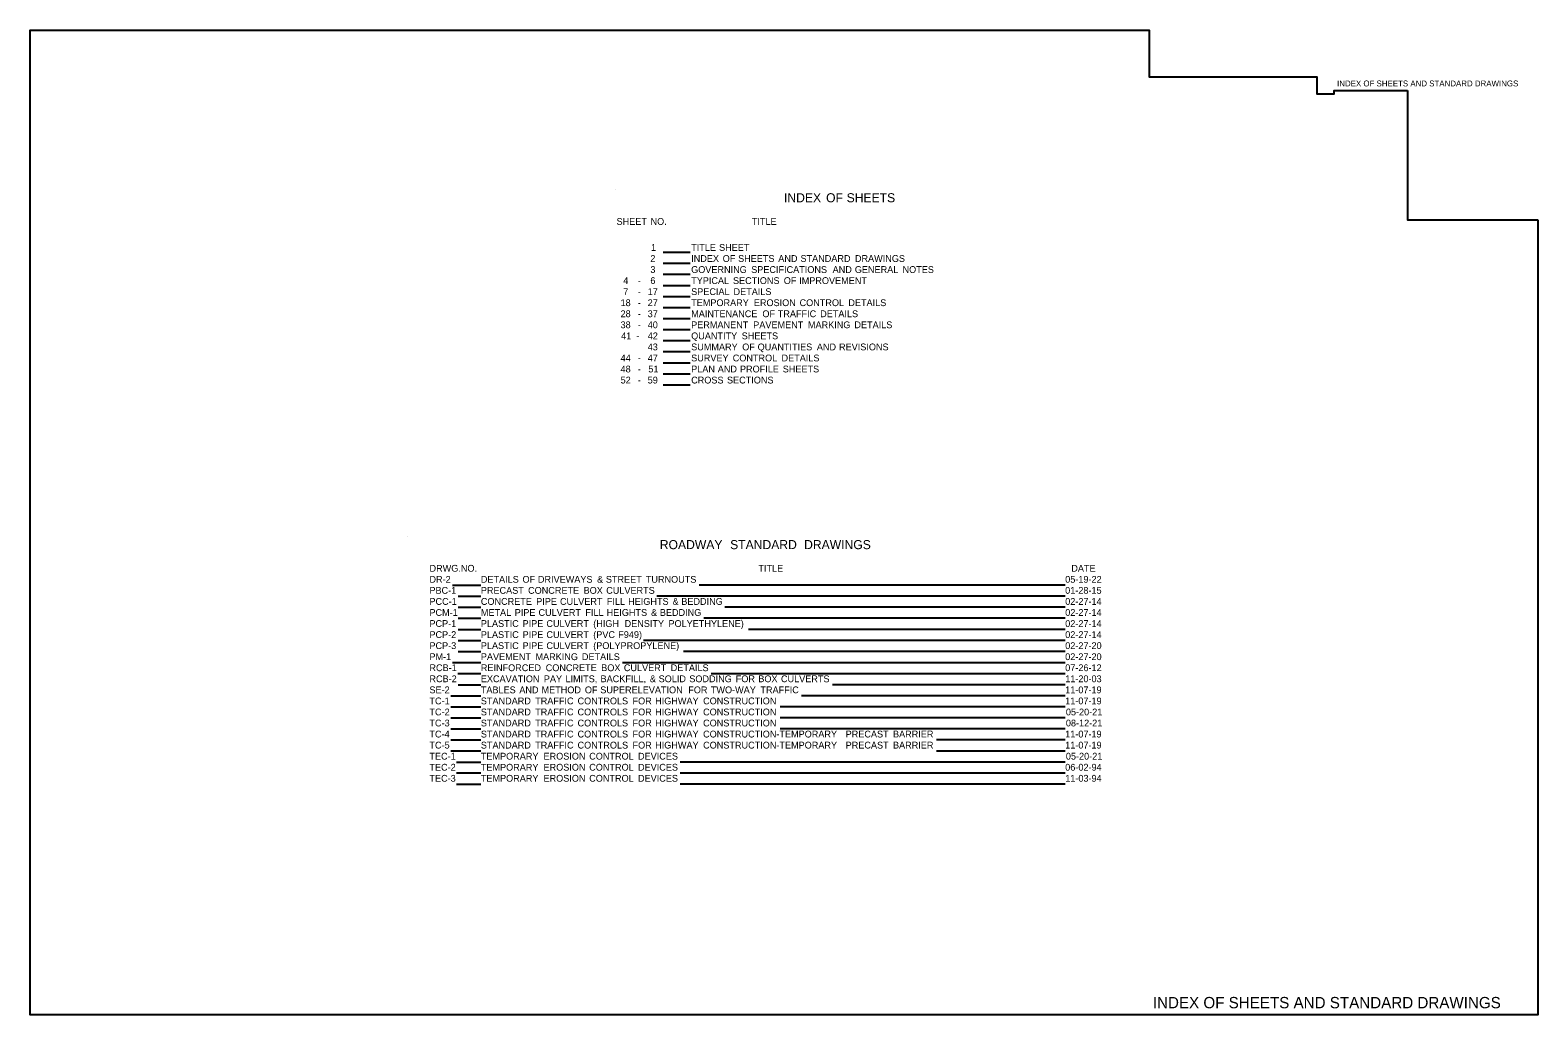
# Model space of a CAD drawing. Extents: x 1955683 to 1956002, y 566394 to 566602.
import ezdxf

# ---------------------------------------------------------------- set-up
doc = ezdxf.new("R2010")
doc.units = 0
for name, color, linetype in [('Default', 7, 'Continuous'), ('R_Border', 7, 'Continuous'), ('R_Border Prem', 7, 'Continuous'), ('STAMP', 7, 'Continuous')]:
    doc.layers.add(name, color=color, linetype=linetype)

msp = doc.modelspace()

# ---------------------------------------------------------------- linework, layer by layer
at = {"layer": 'Default'}
for p, q in [((1955817.31, 566554.97), (1955823.04, 566554.97)), ((1955817.31, 566552.63), (1955823.04, 566552.63)), ((1955817.31, 566550.29), (1955823.04, 566550.29)), ((1955817.31, 566547.95), (1955823.04, 566547.95)), ((1955817.31, 566545.61), (1955823.04, 566545.61)), ((1955817.31, 566543.27), (1955823.04, 566543.27)), ((1955817.31, 566540.93), (1955823.04, 566540.93)), ((1955817.31, 566538.59), (1955823.04, 566538.59)), ((1955817.31, 566536.25), (1955823.04, 566536.25)), ((1955817.31, 566533.91), (1955823.04, 566533.91)), ((1955817.31, 566531.57), (1955823.04, 566531.57)), ((1955817.31, 566529.23), (1955823.04, 566529.23)), ((1955817.31, 566526.89), (1955823.04, 566526.89)), ((1955772.73, 566484.51), (1955778.76, 566484.51)), ((1955824.96, 566484.56), (1955902.43, 566484.56)), ((1955773.96, 566482.16), (1955778.76, 566482.16)), ((1955773.96, 566479.81), (1955778.76, 566479.81)), ((1955815.98, 566482.22), (1955902.43, 566482.22)), ((1955830.36, 566479.87), (1955902.43, 566479.87)), ((1955773.96, 566477.48), (1955778.76, 566477.48)), ((1955825.96, 566477.54), (1955902.43, 566477.54)), ((1955773.96, 566475.12), (1955778.76, 566475.12)), ((1955835.38, 566475.18), (1955902.43, 566475.18)), ((1955773.96, 566472.77), (1955778.76, 566472.77)), ((1955773.96, 566470.44), (1955778.76, 566470.44)), ((1955813.19, 566472.82), (1955902.43, 566472.82)), ((1955821.64, 566470.5), (1955902.43, 566470.5)), ((1955772.73, 566468.12), (1955778.76, 566468.12)), ((1955808.71, 566468.13), (1955902.43, 566468.13)), ((1955773.91, 566465.75), (1955778.76, 566465.75)), ((1955773.97, 566463.41), (1955778.76, 566463.41)), ((1955827.48, 566465.81), (1955902.43, 566465.81)), ((1955853.2, 566463.47), (1955902.43, 566463.47)), ((1955772.44, 566461.07), (1955778.76, 566461.07)), ((1955846.61, 566461.13), (1955902.43, 566461.13)), ((1955772.44, 566458.73), (1955778.76, 566458.73)), ((1955842.11, 566458.79), (1955902.43, 566458.79)), ((1955772.44, 566456.39), (1955778.76, 566456.39)), ((1955772.44, 566454.05), (1955778.76, 566454.05)), ((1955842.11, 566456.45), (1955902.43, 566456.45)), ((1955842.11, 566454.11), (1955902.43, 566454.11)), ((1955772.44, 566451.71), (1955778.76, 566451.71)), ((1955875.18, 566451.77), (1955902.43, 566451.77)), ((1955772.44, 566449.37), (1955778.76, 566449.37)), ((1955875.18, 566449.43), (1955902.43, 566449.43)), ((1955773.62, 566447.03), (1955778.76, 566447.03)), ((1955773.62, 566444.73), (1955778.76, 566444.73)), ((1955820.96, 566447.09), (1955902.43, 566447.09)), ((1955820.96, 566444.74), (1955902.43, 566444.75)), ((1955773.62, 566442.35), (1955778.76, 566442.35)), ((1955820.96, 566442.4), (1955902.43, 566442.41))]:
    msp.add_line(p, q, dxfattribs=at)
at = {"layer": 'R_Border'}
for p, q in [((1955807.24, 566568.3), (1955807.24, 566568.3)), ((1955763.31, 566494.88), (1955763.31, 566494.88))]:
    msp.add_line(p, q, dxfattribs=at)
at = {"layer": 'R_Border Prem'}
for points in [[(1956002.45, 566561.79), (1956002.45, 566393.51), (1955683.38, 566393.51), (1955683.38, 566601.97), (1955920.19, 566601.97), (1955920.19, 566592.09), (1955955.71, 566592.09), (1955955.71, 566588.52), (1955959.35, 566588.52), (1955959.35, 566589.17), (1955974.89, 566589.17)], [(1955974.89, 566589.17), (1955974.89, 566561.79), (1956002.45, 566561.79)]]:
    msp.add_lwpolyline(points, dxfattribs=at)

# ---------------------------------------------------------------- texts
at = {"layer": 'Default'}
for s, height, p in [('INDEX', 1.92, (1955842.92, 566565.53)), (' OF', 1.92, (1955851.11, 566565.53)), (' SHEETS', 1.92, (1955855.46, 566565.53)), ('SHEET', 1.44, (1955807.48, 566560.75)), (' NO.', 1.44, (1955814.14, 566560.75)), ('                        TITLE', 1.44, (1955823.27, 566560.75)), ('1', 1.44, (1955814.77, 566555.25)), ('TITLE', 1.44, (1955823.27, 566555.25)), (' SHEET', 1.44, (1955828.64, 566555.25)), ('2', 1.44, (1955814.63, 566552.91)), ('INDEX', 1.44, (1955823.27, 566552.91)), (' OF', 1.44, (1955829.41, 566552.91)), (' SHEETS', 1.44, (1955832.67, 566552.91)), (' AND', 1.44, (1955841.17, 566552.91)), (' STANDARD', 1.44, (1955845.87, 566552.91)), (' DRAWINGS', 1.44, (1955857.39, 566552.91)), ('4', 1.44, (1955808.9, 566548.23)), ('3', 1.44, (1955814.63, 566550.57)), ('6', 1.44, (1955814.63, 566548.23)), ('TYPICAL', 1.44, (1955823.27, 566548.23)), ('GOVERNING', 1.44, (1955823.27, 566550.57)), (' SECTIONS', 1.44, (1955831.59, 566548.23)), (' SPECIFICATIONS', 1.44, (1955835.44, 566550.57)), (' OF', 1.44, (1955842.33, 566548.23)), (' IMPROVEMENT', 1.44, (1955845.59, 566548.23)), (' AND', 1.44, (1955852.67, 566550.57)), (' GENERAL', 1.44, (1955857.37, 566550.57)), (' NOTES', 1.44, (1955867.47, 566550.57)), ('7', 1.44, (1955808.89, 566545.89)), ('-', 1.44, (1955811.97, 566548.23)), ('-', 1.44, (1955811.97, 566545.89)), ('17', 1.44, (1955814.07, 566545.89)), ('SPECIAL', 1.44, (1955823.27, 566545.89)), (' DETAILS', 1.44, (1955831.7, 566545.89)), ('18', 1.44, (1955808.33, 566543.55)), ('-', 1.44, (1955811.97, 566543.55)), ('27', 1.44, (1955814.07, 566543.55)), ('TEMPORARY', 1.44, (1955823.27, 566543.55)), (' EROSION', 1.44, (1955836, 566543.55)), (' CONTROL', 1.44, (1955845.68, 566543.55)), (' DETAILS', 1.44, (1955856, 566543.55)), ('38', 1.44, (1955808.33, 566538.87)), ('28', 1.44, (1955808.33, 566541.21)), ('-', 1.44, (1955811.97, 566541.21)), ('40', 1.44, (1955814.07, 566538.87)), ('37', 1.44, (1955814.07, 566541.21)), ('MAINTENANCE', 1.44, (1955823.27, 566541.21)), ('PERMANENT', 1.44, (1955823.27, 566538.87)), (' PAVEMENT', 1.44, (1955835.87, 566538.87)), (' OF', 1.44, (1955837.81, 566541.21)), (' TRAFFIC', 1.44, (1955841.07, 566541.21)), (' MARKING', 1.44, (1955847.45, 566538.87)), (' DETAILS', 1.44, (1955850.04, 566541.21)), (' DETAILS', 1.44, (1955857.28, 566538.87)), ('    41  -', 1.44, (1955806.31, 566536.53)), ('-', 1.44, (1955811.97, 566538.87)), ('42', 1.44, (1955814.08, 566536.53)), ('QUANTITY', 1.44, (1955823.27, 566536.53)), (' SHEETS', 1.44, (1955833.43, 566536.53)), ('43', 1.44, (1955814.07, 566534.19)), ('SUMMARY', 1.44, (1955823.27, 566534.19)), (' OF', 1.44, (1955833.54, 566534.19)), (' QUANTITIES', 1.44, (1955836.8, 566534.19)), (' AND', 1.44, (1955849.33, 566534.19)), (' REVISIONS', 1.44, (1955854.03, 566534.19)), ('44', 1.44, (1955808.34, 566531.85)), ('48', 1.44, (1955808.33, 566529.51)), ('-', 1.44, (1955811.97, 566531.85)), ('47', 1.44, (1955814.07, 566531.85)), ('51', 1.44, (1955814.21, 566529.51)), ('SURVEY', 1.44, (1955823.27, 566531.85)), ('PLAN', 1.44, (1955823.27, 566529.51)), (' AND', 1.44, (1955828.36, 566529.51)), (' CONTROL', 1.44, (1955831.53, 566531.85)), (' PROFILE', 1.44, (1955833.06, 566529.51)), (' DETAILS', 1.44, (1955841.86, 566531.85)), (' SHEETS', 1.44, (1955842.12, 566529.51)), ('52', 1.44, (1955808.34, 566527.17)), ('-', 1.44, (1955811.97, 566529.51)), ('-', 1.44, (1955811.97, 566527.17)), ('59', 1.44, (1955814.07, 566527.17)), ('CROSS', 1.44, (1955823.27, 566527.17)), (' SECTIONS', 1.44, (1955830.32, 566527.17)), ('ROADWAY', 1.92, (1955816.63, 566492.1)), (' STANDARD', 1.92, (1955830.8, 566492.1)), (' DRAWINGS', 1.92, (1955846.46, 566492.1)), ('DR-2', 1.44, (1955767.88, 566484.99)), ('DRWG.NO.', 1.44, (1955767.9, 566487.33)), ('DETAILS', 1.44, (1955778.76, 566484.99)), (' OF', 1.44, (1955787.04, 566484.99)), (' DRIVEWAYS', 1.44, (1955790.3, 566484.99)), (' &', 1.44, (1955802.83, 566484.99)), (' STREET', 1.44, (1955804.68, 566484.99)), (' TURNOUTS', 1.44, (1955813.14, 566484.99)), ('TITLE', 1.44, (1955837.5, 566487.33)), ('05-19-22', 1.44, (1955902.43, 566484.99)), ('DATE', 1.44, (1955903.72, 566487.33)), ('PBC-1', 1.44, (1955767.88, 566482.65)), ('PRECAST', 1.44, (1955778.76, 566482.65)), (' CONCRETE', 1.44, (1955788.22, 566482.65)), (' BOX', 1.44, (1955799.97, 566482.65)), (' CULVERTS', 1.44, (1955804.76, 566482.65)), ('01-28-15', 1.44, (1955902.42, 566482.65)), ('PCC-1', 1.44, (1955767.88, 566480.31)), ('PCM-1', 1.44, (1955767.88, 566477.97)), ('CONCRETE', 1.44, (1955778.76, 566480.31)), ('METAL', 1.44, (1955778.76, 566477.97)), (' PIPE', 1.44, (1955785.4, 566477.97)), (' PIPE', 1.44, (1955789.94, 566480.31)), (' CULVERT', 1.44, (1955790.43, 566477.97)), (' CULVERT', 1.44, (1955794.98, 566480.31)), (' FILL', 1.44, (1955800.34, 566477.97)), (' HEIGHTS', 1.44, (1955804.85, 566477.97)), (' FILL', 1.44, (1955804.89, 566480.31)), (' HEIGHTS', 1.44, (1955809.4, 566480.31)), (' &', 1.44, (1955814.25, 566477.97)), (' BEDDING', 1.44, (1955816.11, 566477.97)), (' &', 1.44, (1955818.8, 566480.31)), (' BEDDING', 1.44, (1955820.65, 566480.31)), ('02-27-14', 1.44, (1955902.43, 566480.31)), ('02-27-14', 1.44, (1955902.43, 566477.97)), ('PCP-1', 1.44, (1955767.88, 566475.63)), ('PLASTIC', 1.44, (1955778.76, 566475.63)), (' PIPE', 1.44, (1955787.06, 566475.63)), (' CULVERT', 1.44, (1955792.1, 566475.63)), (' (HIGH', 1.44, (1955802.01, 566475.63)), ('  DENSITY', 1.44, (1955808.11, 566475.63)), (' POLYETHYLENE)', 1.44, (1955817.93, 566475.63)), ('02-27-14', 1.44, (1955902.43, 566475.63)), ('PCP-2', 1.44, (1955767.88, 566473.29)), ('PLASTIC', 1.44, (1955778.76, 566473.29)), (' PIPE', 1.44, (1955787.06, 566473.29)), (' CULVERT', 1.44, (1955792.1, 566473.29)), (' (PVC', 1.44, (1955802.01, 566473.29)), (' F949)', 1.44, (1955807.3, 566473.29)), ('02-27-14', 1.44, (1955902.43, 566473.29)), ('PCP-3', 1.44, (1955767.88, 566470.95)), ('PM-1', 1.44, (1955767.88, 566468.61)), ('PLASTIC', 1.44, (1955778.76, 566470.95)), ('PAVEMENT', 1.44, (1955778.76, 566468.61)), (' PIPE', 1.44, (1955787.06, 566470.95)), (' MARKING', 1.44, (1955789.79, 566468.61)), (' CULVERT', 1.44, (1955792.1, 566470.95)), (' DETAILS', 1.44, (1955799.61, 566468.61)), (' (POLYPROPYLENE)', 1.44, (1955802.01, 566470.95)), ('02-27-20', 1.44, (1955902.43, 566470.95)), ('02-27-20', 1.44, (1955902.43, 566468.61)), ('RCB-1', 1.44, (1955767.88, 566466.27)), ('REINFORCED', 1.44, (1955778.76, 566466.27)), (' CONCRETE', 1.44, (1955791.95, 566466.27)), (' BOX', 1.44, (1955803.7, 566466.27)), (' CULVERT', 1.44, (1955808.49, 566466.27)), (' DETAILS', 1.44, (1955818.4, 566466.27)), ('07-26-12', 1.44, (1955902.43, 566466.27)), ('RCB-2', 1.44, (1955767.88, 566463.93)), ('EXCAVATION', 1.44, (1955778.76, 566463.93)), (' PAY', 1.44, (1955791.56, 566463.93)), (' LIMITS,', 1.44, (1955796.13, 566463.93)), (' BACKFILL,', 1.44, (1955803.56, 566463.93)), (' &', 1.44, (1955814, 566463.93)), (' SOLID', 1.44, (1955815.85, 566463.93)), (' SODDING', 1.44, (1955822.34, 566463.93)), (' FOR', 1.44, (1955832.17, 566463.93)), (' BOX', 1.44, (1955836.95, 566463.93)), (' CULVERTS', 1.44, (1955841.74, 566463.93)), ('11-20-03', 1.44, (1955902.43, 566463.93)), ('TC-1', 1.44, (1955767.88, 566459.25)), ('SE-2', 1.44, (1955767.88, 566461.59)), ('TABLES', 1.44, (1955778.76, 566461.59)), ('STANDARD', 1.44, (1955778.76, 566459.25)), (' AND', 1.44, (1955786.37, 566461.59)), (' TRAFFIC', 1.44, (1955789.72, 566459.25)), (' METHOD', 1.44, (1955791.07, 566461.59)), (' CONTROLS', 1.44, (1955798.69, 566459.25)), (' OF', 1.44, (1955800.24, 566461.59)), (' SUPERELEVATION', 1.44, (1955803.5, 566461.59)), (' FOR', 1.44, (1955810.33, 566459.25)), (' HIGHWAY', 1.44, (1955815.11, 566459.25)), (' FOR', 1.44, (1955822.12, 566461.59)), (' CONSTRUCTION', 1.44, (1955825.26, 566459.25)), (' TWO-WAY', 1.44, (1955826.9, 566461.59)), (' TRAFFIC', 1.44, (1955837.39, 566461.59)), ('11-07-19', 1.44, (1955902.42, 566461.59)), ('11-07-19', 1.44, (1955902.42, 566459.25)), ('TC-2', 1.44, (1955767.88, 566456.91)), ('STANDARD', 1.44, (1955778.76, 566456.91)), (' TRAFFIC', 1.44, (1955789.72, 566456.91)), (' CONTROLS', 1.44, (1955798.69, 566456.91)), (' FOR', 1.44, (1955810.33, 566456.91)), (' HIGHWAY', 1.44, (1955815.11, 566456.91)), (' CONSTRUCTION', 1.44, (1955825.26, 566456.91)), ('05-20-21', 1.44, (1955902.57, 566456.91)), ('TC-3', 1.44, (1955767.88, 566454.57)), ('STANDARD', 1.44, (1955778.76, 566454.57)), (' TRAFFIC', 1.44, (1955789.72, 566454.57)), (' CONTROLS', 1.44, (1955798.69, 566454.57)), (' FOR', 1.44, (1955810.33, 566454.57)), (' HIGHWAY', 1.44, (1955815.11, 566454.57)), (' CONSTRUCTION', 1.44, (1955825.26, 566454.57)), ('08-12-21', 1.44, (1955902.57, 566454.57)), ('TC-4', 1.44, (1955767.88, 566452.23)), ('TC-5', 1.44, (1955767.88, 566449.89)), ('STANDARD', 1.44, (1955778.76, 566452.23)), ('STANDARD', 1.44, (1955778.76, 566449.89)), (' TRAFFIC', 1.44, (1955789.72, 566452.23)), (' TRAFFIC', 1.44, (1955789.72, 566449.89)), (' CONTROLS', 1.44, (1955798.69, 566452.23)), (' CONTROLS', 1.44, (1955798.69, 566449.89)), (' FOR', 1.44, (1955810.33, 566452.23)), (' FOR', 1.44, (1955810.33, 566449.89)), (' HIGHWAY', 1.44, (1955815.11, 566452.23)), (' HIGHWAY', 1.44, (1955815.11, 566449.89)), (' CONSTRUCTION-TEMPORARY', 1.44, (1955825.26, 566452.23)), (' CONSTRUCTION-TEMPORARY', 1.44, (1955825.26, 566449.89)), (' PRECAST', 1.44, (1955855.43, 566452.23)), (' PRECAST', 1.44, (1955855.43, 566449.89)), (' BARRIER', 1.44, (1955865.45, 566452.23)), (' BARRIER', 1.44, (1955865.45, 566449.89)), ('11-07-19', 1.44, (1955902.42, 566452.23)), ('11-07-19', 1.44, (1955902.42, 566449.89)), ('TEC-1', 1.44, (1955767.88, 566447.55)), ('TEMPORARY', 1.44, (1955778.76, 566447.55)), (' EROSION', 1.44, (1955791.49, 566447.55)), (' CONTROL', 1.44, (1955801.16, 566447.55)), (' DEVICES', 1.44, (1955811.49, 566447.55)), ('05-20-21', 1.44, (1955902.57, 566447.55)), ('TEC-2', 1.44, (1955767.88, 566445.21)), ('TEC-3', 1.44, (1955767.88, 566442.87)), ('TEMPORARY', 1.44, (1955778.76, 566445.21)), ('TEMPORARY', 1.44, (1955778.76, 566442.87)), (' EROSION', 1.44, (1955791.49, 566445.21)), (' EROSION', 1.44, (1955791.49, 566442.87)), (' CONTROL', 1.44, (1955801.16, 566445.21)), (' CONTROL', 1.44, (1955801.16, 566442.87)), (' DEVICES', 1.44, (1955811.49, 566445.21)), (' DEVICES', 1.44, (1955811.49, 566442.87)), ('06-02-94', 1.44, (1955902.43, 566445.21)), ('11-03-94', 1.44, (1955902.43, 566442.87))]:
    msp.add_text(s, height=height, dxfattribs=at).set_placement(p)
at = {"layer": 'R_Border'}
msp.add_text('INDEX OF SHEETS AND STANDARD DRAWINGS', height=2.4, rotation=0, dxfattribs=at).set_placement((1955920.97, 566394.9))
at = {"layer": 'STAMP'}
msp.add_text('INDEX OF SHEETS AND STANDARD DRAWINGS', height=1.25, rotation=360, dxfattribs=at).set_placement((1955959.96, 566590.06))

doc.saveas('drawing.dxf')
